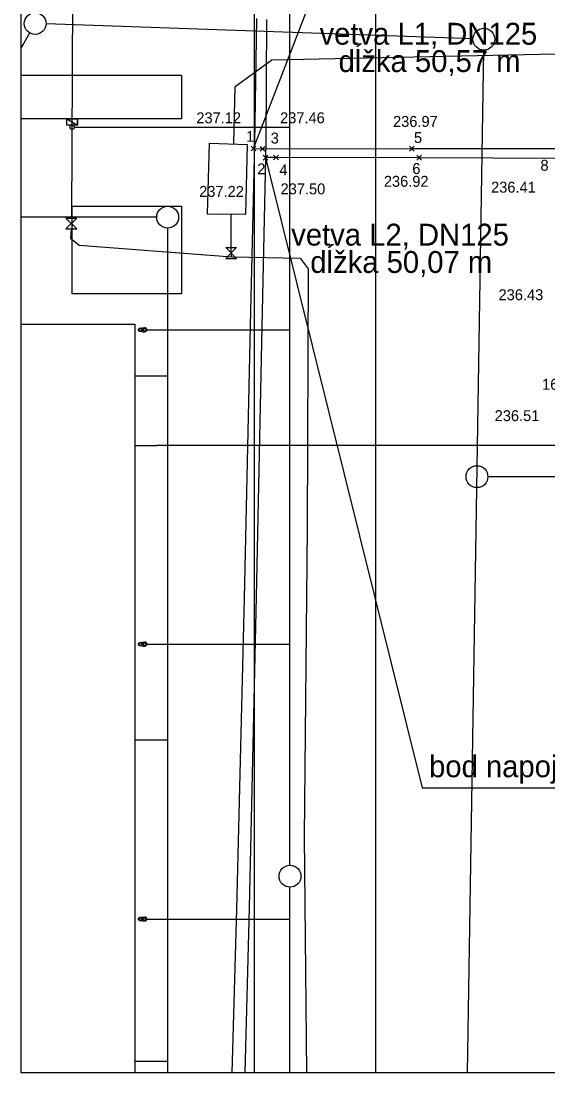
# Model space of a CAD drawing. Extents: x -263964 to -263859, y -1242287 to -1242158.
# Drawn here: x -263964.31 to -263940.2, y -1242232.02 to -1242183.91 of the extents above; entities that cross this region are included whole.
import ezdxf

# ---------------------------------------------------------------- set-up
doc = ezdxf.new("R2010")
doc.units = 0
for name, color, linetype in [('BODY_SYMBOL_A_CISLO', 7, 'Continuous'), ('BODY_VYSKA', 7, 'Continuous'), ('KFA_2D_JESTVUJUCE_IS_DSP', 7, 'Continuous'), ('KFA_2D_SITUACIA_DSP', 7, 'Continuous'), ('KFA_JESTVUJUCI_HORUCOVOD', 7, 'Continuous'), ('KFA_SO_80-1_HORUCOVOD_TRASA', 7, 'Continuous'), ('POPIS', 7, 'Continuous'), ('RAM_NA_TLAC_A3_1-250', 7, 'Continuous')]:
    doc.layers.add(name, color=color, linetype=linetype)

msp = doc.modelspace()

# ---------------------------------------------------------------- linework, layer by layer
at = {"layer": 'BODY_SYMBOL_A_CISLO'}
for p, q in [((-263953.78, -1242189.85), (-263953.559, -1242189.63)), ((-263953.559, -1242189.85), (-263953.78, -1242189.63)), ((-263953.371, -1242189.87), (-263953.149, -1242189.65)), ((-263953.149, -1242189.87), (-263953.371, -1242189.65)), ((-263953.231, -1242190.271), (-263953.009, -1242190.049)), ((-263953.009, -1242190.271), (-263953.231, -1242190.049)), ((-263952.751, -1242190.261), (-263952.53, -1242190.039)), ((-263952.53, -1242190.261), (-263952.751, -1242190.039)), ((-263946.535, -1242189.859), (-263946.313, -1242189.637)), ((-263946.313, -1242189.859), (-263946.535, -1242189.637)), ((-263946.199, -1242190.272), (-263945.978, -1242190.052)), ((-263945.978, -1242190.272), (-263946.199, -1242190.052))]:
    msp.add_line(p, q, dxfattribs=at)
at = {"layer": 'KFA_2D_JESTVUJUCE_IS_DSP'}
for p, q in [((-263961.81, -1242157.773), (-263961.999, -1242192.922)), ((-263943.628, -1242184.728), (-263963.161, -1242184.046)), ((-263963.914, -1242184.46), (-263964.307, -1242185.132)), ((-263943.878, -1242232.023), (-263943.136, -1242185.245)), ((-263954.509, -1242186.913), (-263952.832, -1242185.692)), ((-263952.832, -1242185.692), (-263937.488, -1242185.363)), ((-263954.57, -1242189.535), (-263954.509, -1242186.913)), ((-263955.775, -1242192.739), (-263955.679, -1242189.503)), ((-263955.679, -1242189.503), (-263953.955, -1242189.552)), ((-263953.955, -1242189.552), (-263954.033, -1242192.766)), ((-263962.251, -1242192.922), (-263961.751, -1242192.922)), ((-263961.751, -1242192.922), (-263962.251, -1242193.422)), ((-263961.751, -1242193.422), (-263962.251, -1242192.922)), ((-263954.033, -1242192.766), (-263955.775, -1242192.739)), ((-263954.693, -1242194.518), (-263954.696, -1242192.756)), ((-263962.251, -1242193.422), (-263961.751, -1242193.422)), ((-263962.017, -1242193.422), (-263962.046, -1242193.838)), ((-263962.046, -1242193.838), (-263961.65, -1242194.164)), ((-263961.65, -1242194.164), (-263954.663, -1242194.7)), ((-263954.943, -1242194.268), (-263954.443, -1242194.268)), ((-263954.443, -1242194.268), (-263954.943, -1242194.768)), ((-263954.443, -1242194.768), (-263954.943, -1242194.268)), ((-263954.943, -1242194.768), (-263954.443, -1242194.768)), ((-263954.663, -1242194.7), (-263954.693, -1242194.518)), ((-263954.663, -1242194.7), (-263951.539, -1242194.754)), ((-263951.539, -1242194.754), (-263951.176, -1242195.243)), ((-263951.176, -1242195.243), (-263951.207, -1242207.105)), ((-263951.207, -1242207.105), (-263951.356, -1242221.201)), ((-263951.356, -1242221.201), (-263951.239, -1242232.023))]:
    msp.add_line(p, q, dxfattribs=at)
for centre in [(-263963.661, -1242184.028), (-263943.128, -1242184.745)]:
    msp.add_circle(centre, 0.5, dxfattribs=at)
at = {"layer": 'KFA_2D_SITUACIA_DSP'}
for p, q in [((-263953.617, -1242232.023), (-263953.617, -1242157.773)), ((-263948.093, -1242157.773), (-263948.093, -1242232.023)), ((-263952, -1242222.527), (-263952, -1242182)), ((-263964.307, -1242186.382), (-263956.968, -1242186.382)), ((-263956.968, -1242186.382), (-263956.968, -1242188.382)), ((-263956.968, -1242188.382), (-263964.307, -1242188.382)), ((-263962.218, -1242188.382), (-263961.718, -1242188.382)), ((-263962.218, -1242188.672), (-263962.218, -1242188.382)), ((-263962.218, -1242188.382), (-263961.718, -1242188.672)), ((-263962.218, -1242188.382), (-263961.718, -1242188.672)), ((-263961.718, -1242188.382), (-263962.218, -1242188.382)), ((-263961.718, -1242188.382), (-263961.718, -1242188.672)), ((-263961.718, -1242188.672), (-263961.718, -1242188.382)), ((-263961.718, -1242188.672), (-263962.218, -1242188.672)), ((-263961.868, -1242188.772), (-263952, -1242188.772)), ((-263961.968, -1242192.382), (-263956.968, -1242192.382)), ((-263961.968, -1242196.382), (-263961.968, -1242192.382)), ((-263956.968, -1242192.382), (-263956.968, -1242196.382)), ((-263958.097, -1242192.883), (-263964.307, -1242192.883)), ((-263957.597, -1242232.023), (-263957.597, -1242193.383)), ((-263956.968, -1242196.382), (-263961.968, -1242196.382)), ((-263964.307, -1242197.782), (-263959.093, -1242197.782)), ((-263964.307, -1242197.782), (-263959.097, -1242197.782)), ((-263964.307, -1242197.782), (-263959.097, -1242197.782)), ((-263959.097, -1242197.782), (-263959.095, -1242232.023)), ((-263959.097, -1242197.782), (-263959.097, -1242232.023)), ((-263959.093, -1242197.782), (-263959.093, -1242232.023)), ((-263958.799, -1242197.962), (-263958.762, -1242197.962)), ((-263958.799, -1242198.102), (-263958.762, -1242198.102)), ((-263958.762, -1242197.962), (-263958.742, -1242197.942)), ((-263958.762, -1242198.102), (-263958.742, -1242198.122)), ((-263958.742, -1242197.942), (-263958.637, -1242197.942)), ((-263958.742, -1242198.122), (-263958.637, -1242198.122)), ((-263958.575, -1242198.032), (-263952, -1242198.032)), ((-263959.097, -1242200.132), (-263957.597, -1242200.132)), ((-263959.097, -1242203.332), (-263958.097, -1242203.332)), ((-263924.893, -1242203.332), (-263958.097, -1242203.332)), ((-263938.393, -1242204.752), (-263942.945, -1242204.752)), ((-263958.799, -1242212.337), (-263958.762, -1242212.337)), ((-263958.799, -1242212.477), (-263958.762, -1242212.477)), ((-263958.762, -1242212.337), (-263958.742, -1242212.317)), ((-263958.762, -1242212.477), (-263958.742, -1242212.497)), ((-263958.742, -1242212.317), (-263958.637, -1242212.317)), ((-263958.742, -1242212.497), (-263958.637, -1242212.497)), ((-263958.575, -1242212.407), (-263952, -1242212.407)), ((-263959.097, -1242216.782), (-263957.597, -1242216.782)), ((-263952, -1242232.023), (-263952, -1242223.527)), ((-263958.799, -1242224.912), (-263958.762, -1242224.912)), ((-263958.799, -1242225.052), (-263958.762, -1242225.052)), ((-263958.762, -1242224.912), (-263958.742, -1242224.892)), ((-263958.762, -1242225.052), (-263958.742, -1242225.072)), ((-263958.742, -1242224.892), (-263958.637, -1242224.892)), ((-263958.742, -1242225.072), (-263958.637, -1242225.072)), ((-263958.575, -1242224.982), (-263952, -1242224.982)), ((-263959.097, -1242231.482), (-263957.597, -1242231.482))]:
    msp.add_line(p, q, dxfattribs=at)
for centre, radius in [((-263961.968, -1242188.772), 0.1), ((-263957.597, -1242192.883), 0.5), ((-263958.847, -1242198.032), 0.085), ((-263958.847, -1242198.032), 0.0625), ((-263958.637, -1242198.032), 0.0625), ((-263943.445, -1242204.752), 0.5), ((-263958.847, -1242212.407), 0.085), ((-263958.847, -1242212.407), 0.0625), ((-263958.637, -1242212.407), 0.0625), ((-263952, -1242223.027), 0.5), ((-263958.847, -1242224.982), 0.085), ((-263958.847, -1242224.982), 0.0625), ((-263958.637, -1242224.982), 0.0625)]:
    msp.add_circle(centre, radius, dxfattribs=at)
for centre in [(-263958.637, -1242198.032), (-263958.637, -1242212.407), (-263958.637, -1242224.982)]:
    msp.add_arc(centre, 0.09, 270, 90, dxfattribs=at)
at = {"layer": 'KFA_JESTVUJUCI_HORUCOVOD'}
for p, q in [((-263953.528, -1242183.799), (-263953.63, -1242189.514)), ((-263953.083, -1242189.456), (-263953.067, -1242183.845)), ((-263953.63, -1242189.514), (-263953.822, -1242197.849)), ((-263953.266, -1242197.902), (-263953.083, -1242189.456)), ((-263953.822, -1242197.849), (-263954.091, -1242210.31)), ((-263953.525, -1242210.24), (-263953.266, -1242197.902)), ((-263953.851, -1242224.476), (-263953.525, -1242210.24)), ((-263954.091, -1242210.31), (-263954.451, -1242224.536)), ((-263954.451, -1242224.536), (-263954.654, -1242232.023)), ((-263954.052, -1242232.023), (-263953.851, -1242224.476))]:
    msp.add_line(p, q, dxfattribs=at)
at = {"layer": 'KFA_SO_80-1_HORUCOVOD_TRASA'}
for points in [[(-263953.67, -1242189.74), (-263953.26, -1242189.76), (-263946.424, -1242189.748), (-263938.73, -1242189.74), (-263938.56, -1242189.84), (-263938.46, -1242190.02), (-263938.735, -1242195.271), (-263939.03, -1242200.09), (-263938.93, -1242200.28), (-263938.75, -1242200.4), (-263932.57, -1242200.6), (-263927.04, -1242200.73), (-263921.65, -1242200.9), (-263914.05, -1242201.19)], [(-263914.06, -1242201.67), (-263921.71, -1242201.49), (-263927.16, -1242201.34), (-263932.59, -1242201.2), (-263939.23, -1242201), (-263939.43, -1242200.9), (-263939.52, -1242200.73), (-263939.25, -1242195.347), (-263939.04, -1242190.47), (-263939.13, -1242190.33), (-263939.31, -1242190.2), (-263946.089, -1242190.162), (-263952.64, -1242190.15), (-263953.12, -1242190.16)]]:
    msp.add_lwpolyline(points, dxfattribs=at)
at = {"layer": 'POPIS'}
for p, q in [((-263953.666, -1242189.744), (-263949.014, -1242177.664)), ((-263953.122, -1242190.161), (-263945.951, -1242218.975)), ((-263945.951, -1242218.975), (-263924.667, -1242218.975))]:
    msp.add_line(p, q, dxfattribs=at)
at = {"layer": 'RAM_NA_TLAC_A3_1-250'}
msp.add_lwpolyline([(-263964.307, -1242157.773), (-263859.307, -1242157.773), (-263859.307, -1242232.023), (-263964.307, -1242232.023)], close=True, dxfattribs=at)

# ---------------------------------------------------------------- texts
at = {"layer": 'BODY_SYMBOL_A_CISLO'}
for s, p in [('1', (-263954.006, -1242189.434)), ('3', (-263952.882, -1242189.515)), ('5', (-263946.325, -1242189.49)), ('2', (-263953.497, -1242190.922)), ('4', (-263952.486, -1242190.969)), ('6', (-263946.403, -1242190.909)), ('8', (-263940.54, -1242190.759)), ('16', (-263940.465, -1242200.776))]:
    msp.add_text(s, height=0.5, dxfattribs=at).set_placement(p)
at = {"layer": 'BODY_VYSKA'}
for s, p in [('237.12', (-263956.284, -1242188.587)), ('237.46', (-263952.454, -1242188.586)), ('236.97', (-263947.285, -1242188.753)), ('236.92', (-263947.705, -1242191.493)), ('237.22', (-263956.156, -1242191.954)), ('237.50', (-263952.43, -1242191.838)), ('236.41', (-263942.799, -1242191.761)), ('236.43', (-263942.457, -1242196.68)), ('236.51', (-263942.634, -1242202.21))]:
    msp.add_text(s, height=0.5, dxfattribs=at).set_placement(p)
at = {"layer": 'POPIS'}
for s, p in [('vetva L1, DN125', (-263950.648, -1242184.993)), ('dĺžka 50,57 m', (-263949.777, -1242186.243)), ('vetva L2, DN125', (-263951.943, -1242194.182)), ('dĺžka 50,07 m', (-263951.072, -1242195.432)), ('bod napojenia na jestvujúcu trasu', (-263945.637, -1242218.497))]:
    msp.add_text(s, height=1, dxfattribs=at).set_placement(p)

doc.saveas('drawing.dxf')
